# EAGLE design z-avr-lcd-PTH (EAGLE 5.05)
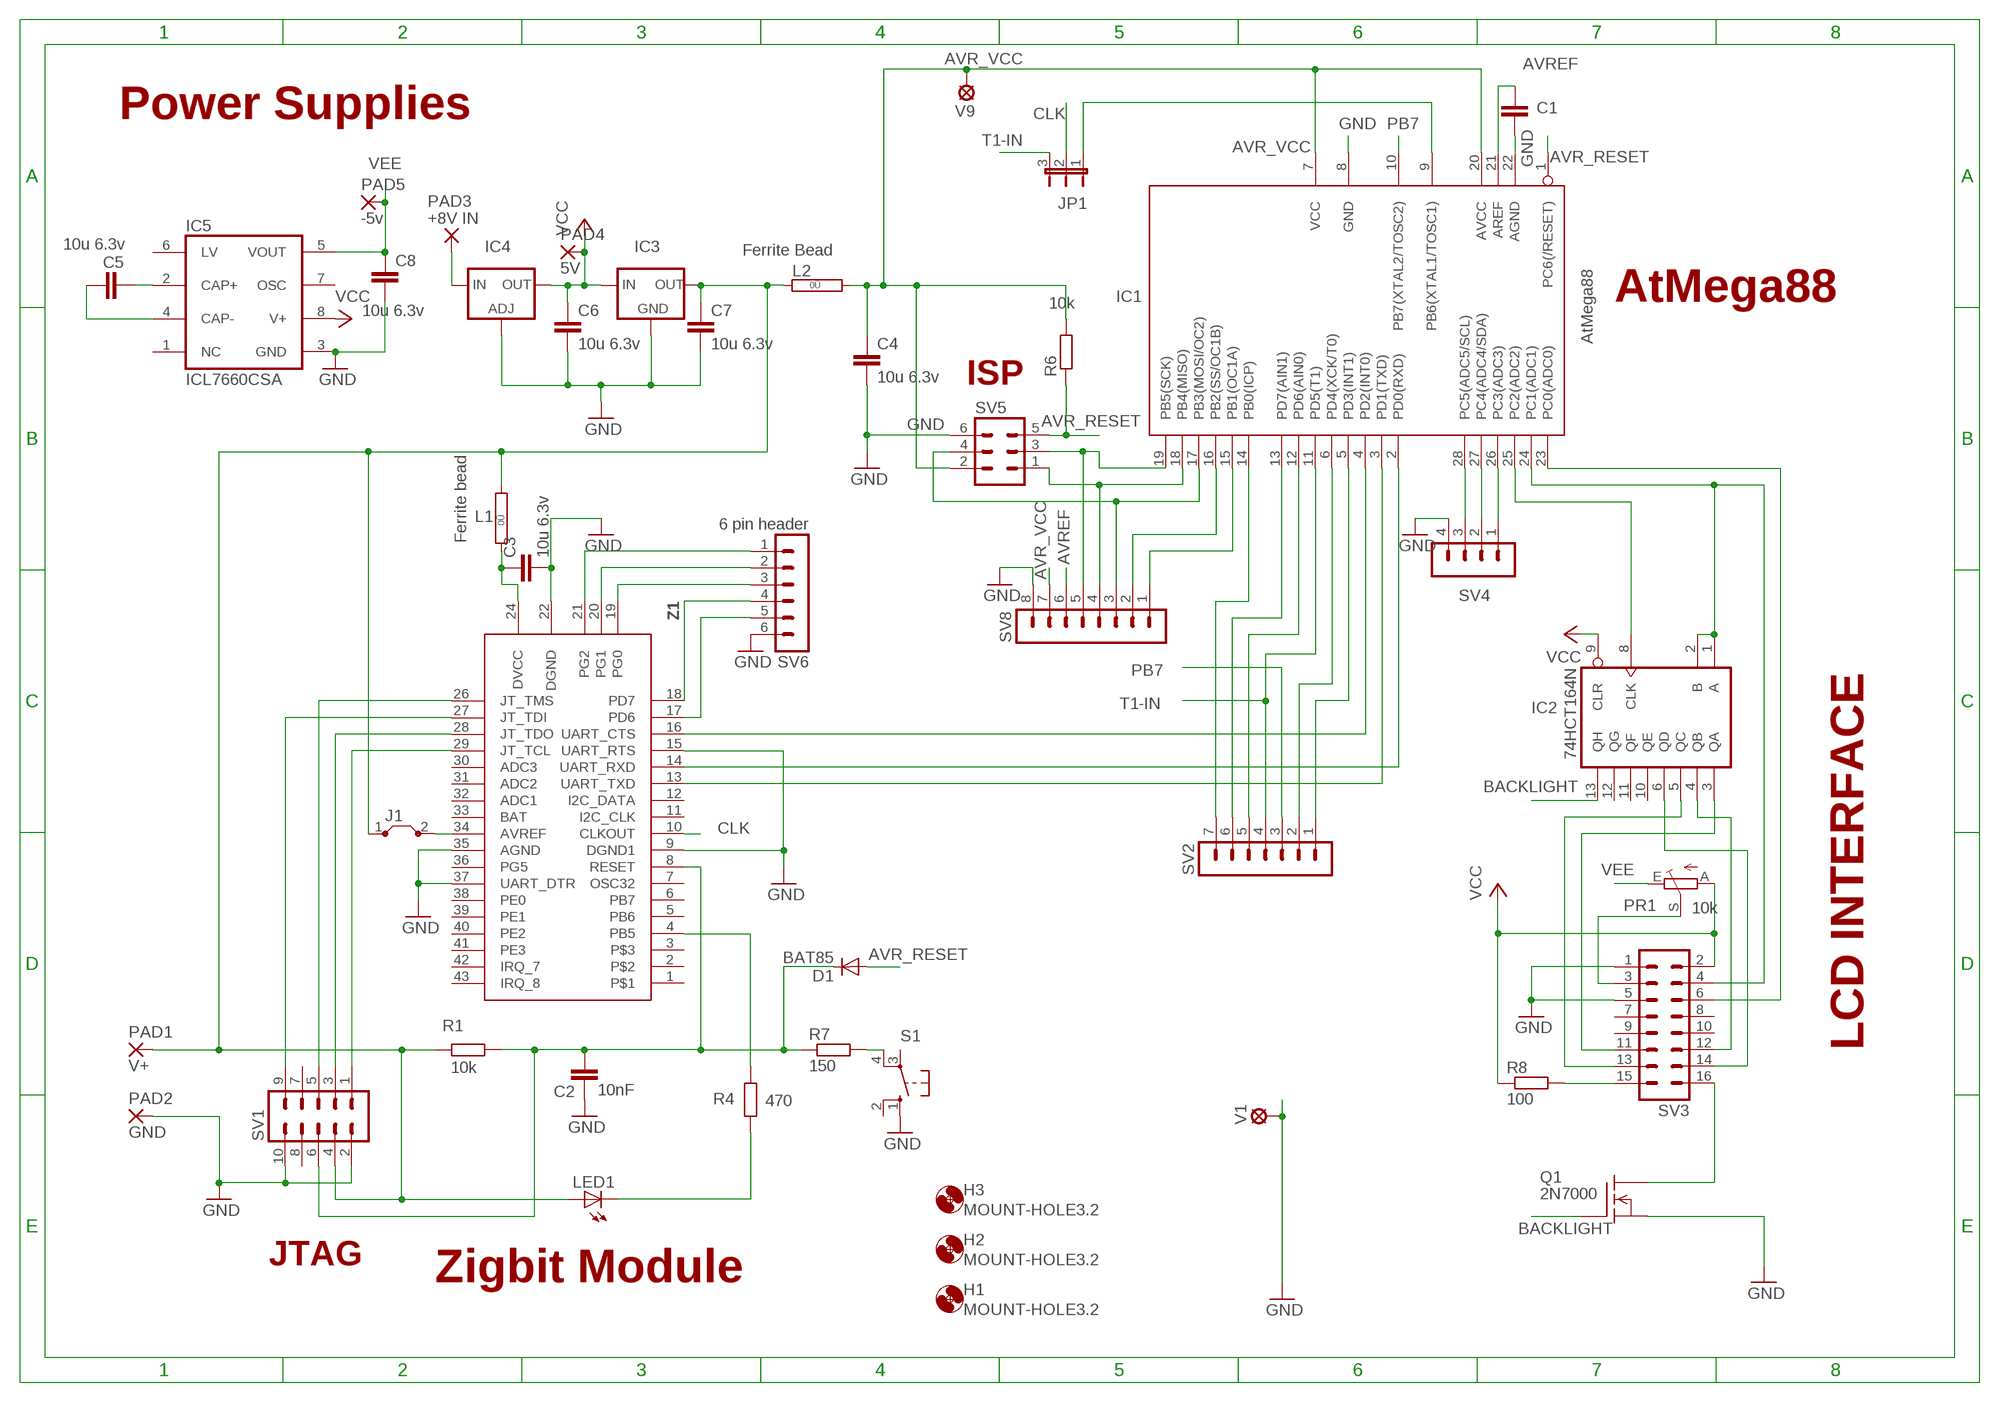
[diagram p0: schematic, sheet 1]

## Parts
C1  10y 6.3v  C-EUC1206  [C1206]
C2  10nF  C5P  [C050-030-075]
C3  10u 6.3v  C-EUC1206  [C1206]
C4  10u 6.3v  C-EUC1206  [C1206]
C5  10u 6.3v  C-EUC1206  [C1206]
C6  10u 6.3v  C-EUC1206  [C1206]
C7  10u 6.3v  C-EUC1206  [C1206]
C8  10u 6.3v  C-EUC1206  [C1206]
D1  BAT85  1N4148  [DO34-7]
H1  MOUNT-HOLE3.2  [3,2]
H2  MOUNT-HOLE3.2  [3,2]
H3  MOUNT-HOLE3.2  [3,2]
IC1  AtMega88  MEGA8-P  [DIL28-3]
IC2  74HCT164N  74ACT164N  [DIL14]
IC3  MC1702-3302E/TO 3.3V LDO VREG  XC63FPT  [TO92]
IC4  LD117ADT50TR  [DPACK]
IC5  ICL7660CSA  [SO08]
J1  J7MM  [07]
JP1  3 way Jumper  JP2E  [JP2]
L1  Ferrite bead  0R  [0R/10]
L2  Ferrite Bead  JUMPER_0R  [JUMPER_0R/10]
LED1  3MM red LED  LED-3MM3MM  [HLMP-D105]
PAD1  V+  TERMINAL-PAD  [2,54/1,1]
PAD2  GND  TERMINAL-PAD  [2,54/1,1]
PAD3  +8V IN  PAD-TERMINAL  [2,54/1,1]
PAD4  5V  TERMINAL-PAD  [2,54/1,1]
PAD5  -5v  TERMINAL-PAD  [2,54/1,1]
PR1  10k  VAR_RESISTOR_TRIMS63P  [S63P]
Q1  2N7000  [TO92]
R1  10k  R  [0207/10]
R4  470  R  [0207/10]
R6  10k  R  [0207/10]
R7  150  R  [0207/10]
R8  100  R  [0207/10]
S1  BW3-1000 PCB pushbutton  10-XX  [B3F-10XX]
SV1  10 way IDC male horiz mnt  ML10L  [ML10L]
SV2  7 way pin header  MA07-1  [MA07-1]
SV3  16 way IDC male horiz mnt  ML16L  [ML16L]
SV4  4 way pin header  MA04-1  [MA04-1]
SV5  6 way male IDC horiz mnt  ML6L  [ML6L]
SV6  6 pin header  MA06-1  [MA06-1]
SV8  8 way pin header  MA08-1  [MA08-1]
V1  HOLE-VIA"  [1,6/0,8]
V9  HOLE-VIA"  [1,6/0,8]
Z1  ZDM-A1281-A2N  [ZIGSMD]

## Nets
AVR_RESET: D1.A IC1.1(PC6(/RESET)) R6.1 SV5.5
AVR_VCC [supply]: C4.1 IC1.7(VCC) IC1.20(AVCC) L2.2 R6.2 SV5.2 SV8.7 V9.1(MP)
AVREF: C1.1 IC1.21(AREF) SV8.6
BACKLIGHT: IC2.13(QH) Q1.2(G)
CLK: JP1.2 Z1.10(CLKOUT)
GND: C1.2 C2.1 C3.2 C4.2 C6.2 C7.2 C8.2 IC1.8(GND) IC1.22(AGND) IC3.1(GND) IC4.1(ADJ) IC5.3(GND) PAD2.1(P) Q1.3(S) S1.1(S) SV1.2 SV1.10 SV3.1 SV3.5 SV4.4 SV5.6 SV6.6 SV8.8 V1.1(MP) Z1.9(DGND1) Z1.15(UART_RTS) Z1.22(DGND) Z1.35(AGND) Z1.37(UART_DTR)
N$1: IC1.18(PB4(MISO)) SV5.1 SV8.4
N$2: IC1.19(PB5(SCK)) SV5.3 SV8.5
N$3: IC1.24(PC1(ADC1)) IC2.1(A) IC2.2(B) SV3.4
N$4: IC1.25(PC2(ADC2)) IC2.8(CLK)
N$5: IC1.28(PC5(ADC5/SCL)) SV4.3
N$6: R7.2 S1.4(P1)
N$7: IC1.27(PC4(ADC4/SDA)) SV4.2
N$8: IC1.17(PB3(MOSI/OC2)) SV5.4 SV8.3
N$9: SV1.5 Z1.26(JT_TMS)
N$10: SV1.1 Z1.29(JT_TCL)
N$11: SV1.3 Z1.28(JT_TDO)
N$12: IC1.26(PC3(ADC3)) SV4.1
N$13: C2.2 D1.C R1.2 R7.1 SV1.6 Z1.8(RESET)
N$14: IC2.6(QD) SV3.14
N$15: IC1.23(PC0(ADC0)) SV3.6
N$16 [supply]: C7.1 IC3.3(OUT) J1.1 L1.2 L2.1 LED1.A PAD1.1(P) R1.1 SV1.4
N$17: C5.1 IC5.2(CAP+)
N$18: IC1.4(PD2(INT0)) Z1.16(UART_CTS)
N$19: PR1.S SV3.3
N$20: IC1.2(PD0(RXD)) Z1.14(UART_RXD)
N$21: IC1.3(PD1(TXD)) Z1.13(UART_TXD)
N$22: IC2.3(QA) SV3.11
N$23: IC2.4(QB) SV3.12
N$24: IC2.5(QC) SV3.13
N$25: C5.2 IC5.4(CAP-)
N$26: R8.2 SV3.15
N$27: Q1.1(D) SV3.16
N$28: R4.2 Z1.4(PB5)
N$29 [supply]: IC4.3(IN) PAD3.1(P)
N$30: LED1.K(C) R4.1
N$31: SV1.9 Z1.27(JT_TDI)
N$32: IC1.9(PB6(XTAL1/TOSC1)) JP1.1
N$33 [supply]: C3.1 L1.1 Z1.24(DVCC)
N$34: SV6.1 Z1.21(PG2)
N$35: SV6.2 Z1.20(PG1)
N$36: SV6.3 Z1.19(PG0)
N$37: IC1.5(PD3(INT1)) SV2.1
N$38: IC1.15(PB1(OC1A)) SV8.1
N$39: IC1.16(PB2(SS/OC1B)) SV8.2
N$40: IC1.12(PD6(AIN0)) SV2.5
N$41: IC1.13(PD7(AIN1)) SV2.6
N$42: IC1.14(PB0(ICP)) SV2.7
N$43: SV6.4 Z1.18(PD7)
N$44: IC1.6(PD4(XCK/T0)) SV2.2
N$45: SV6.5 Z1.17(PD6)
N$46: J1.2 Z1.34(AVREF)
PB7: IC1.10(PB7(XTAL2/TOSC2)) SV2.3
T1-IN: IC1.11(PD5(T1)) JP1.3 SV2.4
VCC [supply]: C6.1 IC2.9(CLR) IC3.2(IN) IC4.4(OUT) IC5.8(V+) PAD4.1(P) PR1.A R8.1 SV3.2
VEE: C8.1 IC5.5(VOUT) PAD5.1(P) PR1.E
Unconnected: IC2.10(QE) IC2.11(QF) IC2.12(QG) IC5.1(NC) IC5.6(LV) IC5.7(OSC) S1.2(S1) S1.3(P) SV1.7 SV1.8 SV3.7 SV3.8 SV3.9 SV3.10 Z1.1 Z1.2 Z1.3 Z1.5(PB6) Z1.6(PB7) Z1.7(OSC32) Z1.11(I2C_CLK) Z1.12(I2C_DATA) Z1.30(ADC3) Z1.31(ADC2) Z1.32(ADC1) Z1.33(BAT) Z1.36(PG5) Z1.38(PE0) Z1.39(PE1) Z1.40(PE2) Z1.41(PE3) Z1.42(IRQ_7) Z1.43(IRQ_8)

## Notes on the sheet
- Power Supplies
- AtMega88
- ISP
- LCD INTERFACE
- JTAG
- Zigbit Module

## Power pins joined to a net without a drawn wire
GND: IC2.7(GND)
VCC: IC2.14(VCC)

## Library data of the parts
C1 C3-C8 = rcl:C-EU: CAPACITOR, European symbol
C2 = ee2parts:C: Capacitor
D1 = ee2parts:1N4148: DIODE
H1-H3 = holes:MOUNT-HOLE: MOUNTING HOLE with drill center marker
IC1 = atmel:MEGA8-P: MICROCONTROLLER 8 Kbytes FLASH, 1 kbytes SRAM, 512 bytes EEPROM, USART, 4-channel 10 bit ADC, 2-channel 8 bit ADC Pin compatible with Atmega48, ATMega88, ATMega168 Source: avr.lbr
IC2 = 74xx-eu:74*164: 8-bit parallel out SHIFT REGISTER
IC3 = v-reg:XC63FP: Positiv Voltage Regulators www.torex.co.jp/english/product/pro02/pdf/0201_xc62fp.pdf
IC4 = v-reg:LD117A?*: Low drop fixed and adjustable positive voltage regulators 1 A Source: http://www.st.com/stonline/products/literature/ds/7194/ld1117axx.pdf
IC5 = maxim:ICL7660CSA: VOLTAGE CONVERTER
J1 = jumper:J: Bridge
JP1 = jumper:JP2E: JUMPER
L1 = jumper:0R: Bridge 0R 10mm
L2 = z-avr-lcd-noPTH:JUMPER_0R: Bridge 0R 10mm
LED1 = ee2parts:LED-3MM: LED
PAD1 PAD2 PAD4 PAD5 = ee2parts:TERMINAL-PAD: LARGE THROUGH-HOLE PAD
PAD3 = ee2parts:PAD-TERMINAL: LARGE THROUGH-HOLE PAD
PR1 = ee2parts:VAR_RESISTOR_TRIM: Variable resistor / potentiometer Trimmer potentiometer - Note that slider to end makes variable resistance
Q1 = z-avr-lcd-noPTH:2N7000: N-Channel Enhancement MOSFET 200V; 0,16A; 11Ohm
R1 R4 R6-R8 = ee2parts:R: Resistor
S1 = switch-omron:10-XX: OMRON SWITCH
SV1 = con-ml:ML10L: HARTING
SV2 = con-lstb:MA07-1: PIN HEADER
SV3 = con-ml:ML16L: HARTING
SV4 = con-lstb:MA04-1: PIN HEADER
SV5 = con-ml:ML6L: HARTING
SV6 = con-lstb:MA06-1: PIN HEADER
SV8 = con-lstb:MA08-1: PIN HEADER
V1 V9 = ee2parts:HOLE-VIA: FIXED VIA
Z1 = ee2parts:ZDM-A1281-A2

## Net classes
1 supply: width 0.889 mm

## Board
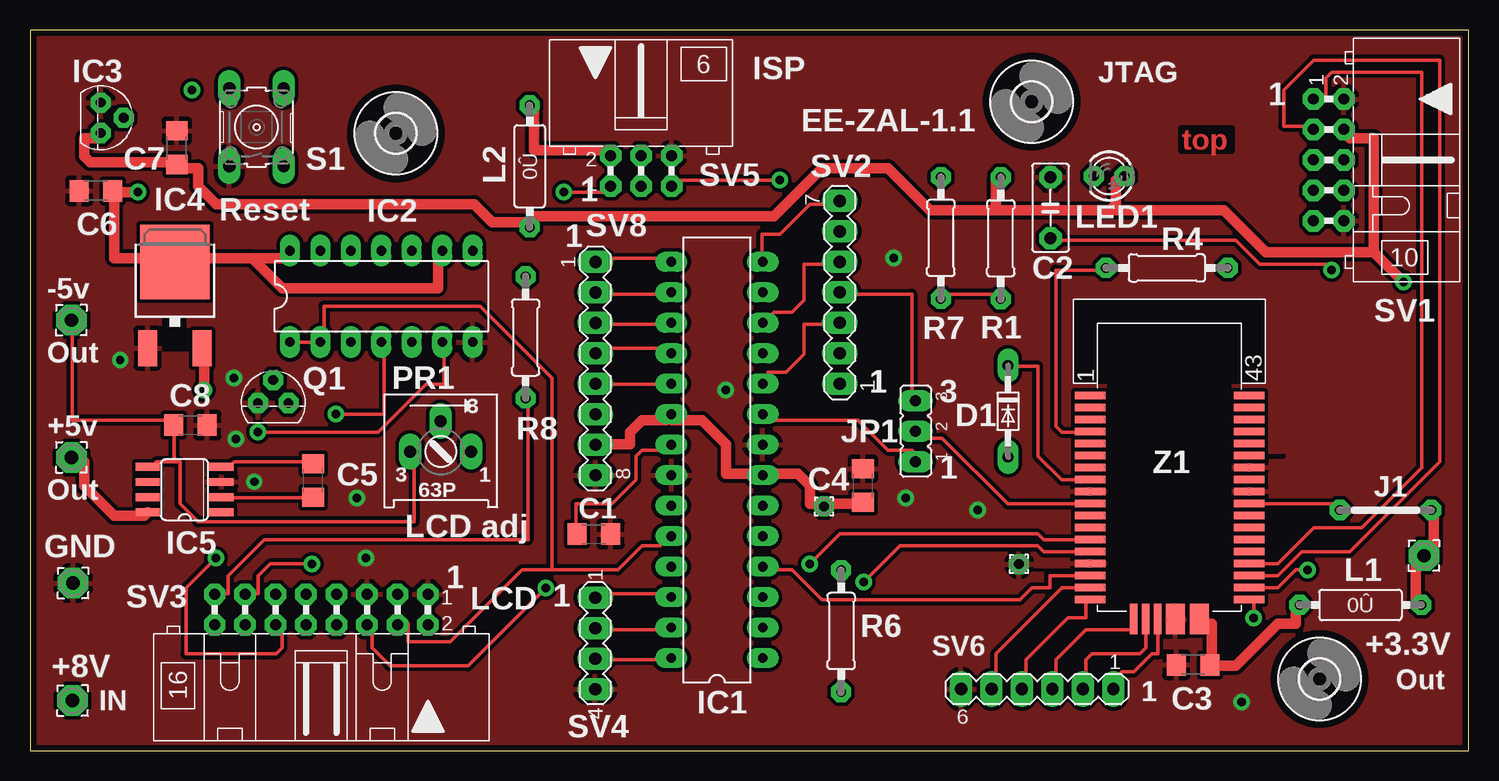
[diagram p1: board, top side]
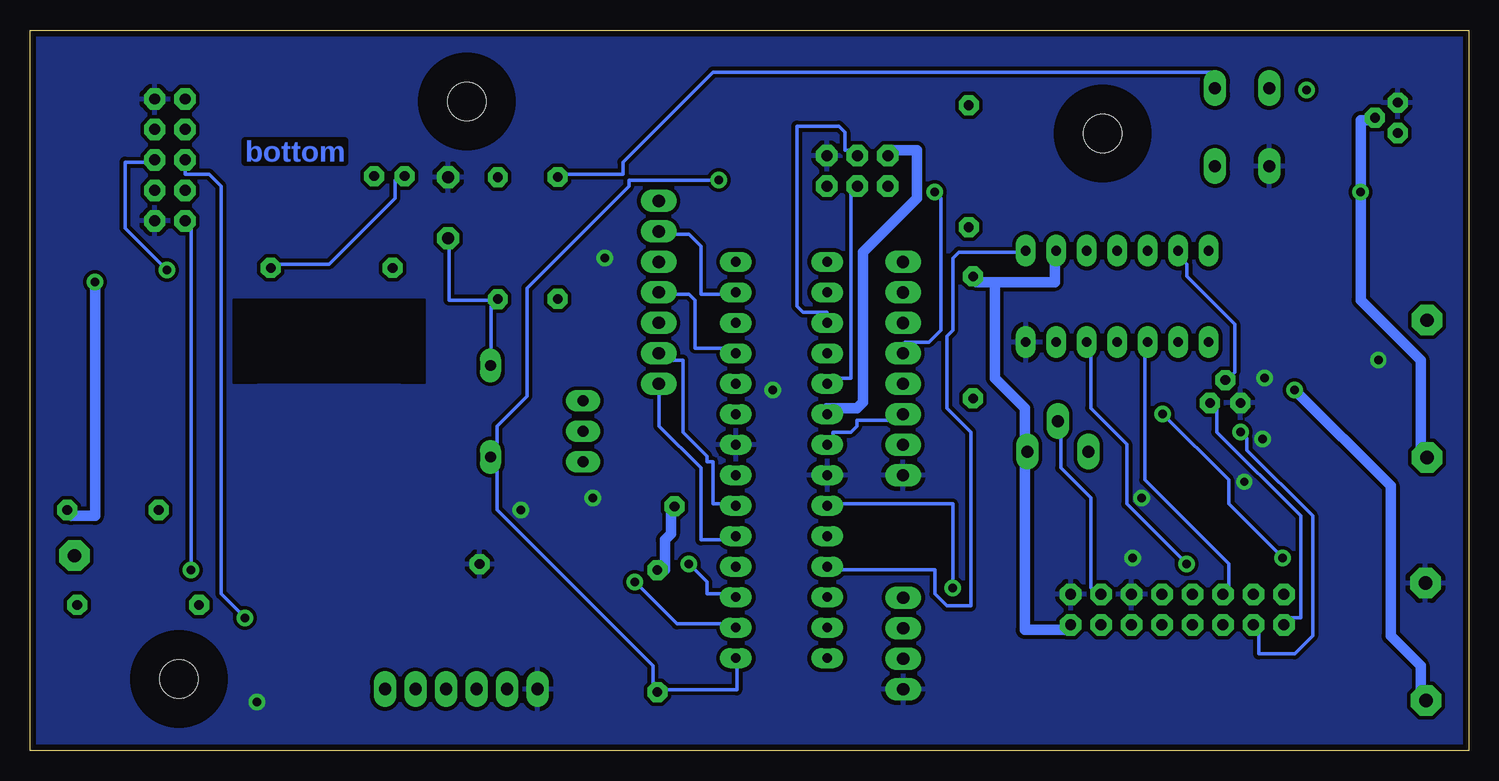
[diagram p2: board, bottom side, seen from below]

Size 119.92 x 60.07 mm. Coordinates in mm from the lower left corner, seen from the top.
Outline: 0,0 119.92,0 119.92,60.07 0,60.07 0,0
Copper layers (1*16): Top 0.035mm / dielectric 1.5mm / Bottom 0.035mm
Design rules "zigbit_rules *": minimum track width 12mil, minimum drill 0.7mm, track to track 12mil, track to pad 12mil, pad to pad 12mil, via to via 12mil, smd to smd 0mil, copper to edge 20mil, drill to drill 10mil, minimum pad ring 17mil, minimum via ring 13mil, stop-mask expansion 0mil, vias tented up to drill 0mil, thermal gap 15mil
tRestrict: area 11,33.3 to 13,36.1; 2 lines

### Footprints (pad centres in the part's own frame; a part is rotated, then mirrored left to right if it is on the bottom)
C1206 = smd 1.6 x 1.8: 1 -1.4,0; 2 1.4,0
C050-030-075 = drill 1 octagon: 1 -2.54,0; 2 2.54,0
DO34-7 = drill 0.9 long: A 3.81,0; C -3.81,0
3,2 = hole 3.2: 0,0
DIL28-3 = drill 0.813 long: 1 -16.51,-3.81; 2 -13.97,-3.81; 3 -11.43,-3.81; 4 -8.89,-3.81; 5 -6.35,-3.81; 6 -3.81,-3.81; 7 -1.27,-3.81; 8 1.27,-3.81; 9 3.81,-3.81; 10 6.35,-3.81; 11 8.89,-3.81; 12 11.43,-3.81; 13 13.97,-3.81; 14 16.51,-3.81; 15 16.51,3.81; 16 13.97,3.81; 17 11.43,3.81; 18 8.89,3.81; 19 6.35,3.81; 20 3.81,3.81; 21 1.27,3.81; 22 -1.27,3.81; 23 -3.81,3.81; 24 -6.35,3.81; 25 -8.89,3.81; 26 -11.43,3.81; 27 -13.97,3.81; 28 -16.51,3.81
DIL14 = drill 0.813 long: 1 -7.62,-3.81; 2 -5.08,-3.81; 3 -2.54,-3.81; 4 0,-3.81; 5 2.54,-3.81; 6 5.08,-3.81; 7 7.62,-3.81; 8 7.62,3.81; 9 5.08,3.81; 10 2.54,3.81; 11 0,3.81; 12 -2.54,3.81; 13 -5.08,3.81; 14 -7.62,3.81
TO92 = drill 0.813 octagon: 1 -1.27,0; 2 0,1.905; 3 1.27,0
DPACK = smd 1.6 x 3: 1 -2.28,-4.8; 3 2.28,-4.8 | smd 5.8 x 6.2: 4 0,2.38
SO08 = smd 0.66 x 2.032: 1 -1.905,-3.073; 2 -0.635,-3.073; 3 0.635,-3.073; 4 1.905,-3.073; 5 1.905,3.073; 6 0.635,3.073; 7 -0.635,3.073; 8 -1.905,3.073
07 = drill 0.813 pad 1.6 octagon: 1 -3.81,0; 2 3.81,0
JP2 = drill 0.914 long: 1 -2.54,0; 2 0,0; 3 2.54,0
0R/10 = drill 0.813 pad 1.6 octagon: 1 -5.08,0; 2 5.08,0
JUMPER_0R/10 = drill 0.813 pad 1.6 octagon: 1 -5.08,0; 2 5.08,0
HLMP-D105 = drill 0.8 octagon: A -1.27,0; K 1.27,0
2,54/1,1 = drill 1.118 pad 2.54 octagon: 1 0,0
S63P = drill 1 long: A 2.54,0; E -2.54,0; S 0,2.54
TO92' = drill 0.813 octagon: 1 1.27,0; 2 0,1.905; 3 -1.27,0
0207/10 = drill 0.8 octagon: 1 -5.08,0; 2 5.08,0
B3F-10XX = drill 1.016 long: 1 -3.251,2.261; 2 3.251,2.261; 3 -3.251,-2.261; 4 3.251,-2.261
ML10L = drill 0.914 octagon: 1 -5.08,-1.27; 2 -5.08,1.27; 3 -2.54,-1.27; 4 -2.54,1.27; 5 0,-1.27; 6 0,1.27; 7 2.54,-1.27; 8 2.54,1.27; 9 5.08,-1.27; 10 5.08,1.27
MA07-1 = drill 1.016 long: 1 -7.62,0; 2 -5.08,0; 3 -2.54,0; 4 0,0; 5 2.54,0; 6 5.08,0; 7 7.62,0
ML16L = drill 0.914 octagon: 1 -8.89,-1.27; 2 -8.89,1.27; 3 -6.35,-1.27; 4 -6.35,1.27; 5 -3.81,-1.27; 6 -3.81,1.27; 7 -1.27,-1.27; 8 -1.27,1.27; 9 1.27,-1.27; 10 1.27,1.27; 11 3.81,-1.27; 12 3.81,1.27; 13 6.35,-1.27; 14 6.35,1.27; 15 8.89,-1.27; 16 8.89,1.27
MA04-1 = drill 1.016 long: 1 -3.81,0; 2 -1.27,0; 3 1.27,0; 4 3.81,0
ML6L = drill 0.914 octagon: 1 -2.54,-1.27; 2 -2.54,1.27; 3 0,-1.27; 4 0,1.27; 5 2.54,-1.27; 6 2.54,1.27
MA06-1 = drill 1.016 long: 1 -6.35,0; 2 -3.81,0; 3 -1.27,0; 4 1.27,0; 5 3.81,0; 6 6.35,0
MA08-1 = drill 1.016 long: 1 -8.89,0; 2 -6.35,0; 3 -3.81,0; 4 -1.27,0; 5 1.27,0; 6 3.81,0; 7 6.35,0; 8 8.89,0
1,6/0,8 = drill 0.813 pad 1.6 octagon: 1 0,0
ZIGSMD = smd 0.635 x 2.54: 1 7,6.635; 2 6,6.635; 3 5,6.635; 4 4,6.635; 5 3,6.635; 6 2,6.635; 7 1,6.635; 8 0,6.635; 9 -1,6.635; 10 -2,6.635; 11 -3,6.635; 12 -4,6.635; 13 -5,6.635; 14 -6,6.635; 15 -7,6.635; 16 -8,6.635; 17 -9,6.635; 18 -10,6.635; 26 -10,-6.635; 27 -9,-6.635; 28 -8,-6.635; 29 -7,-6.635; 30 -6,-6.635; 31 -5,-6.635; 32 -4,-6.635; 33 -3,-6.635; 34 -2,-6.635; 35 -1,-6.635; 36 0,-6.635; 37 1,-6.635; 38 2,-6.635; 39 3,-6.635; 40 4,-6.635; 41 5,-6.635; 42 6,-6.635; 43 7,-6.635 | smd 2.54 x 0.635: 19 -11.635,3; 20 -11.635,2; 21 -11.635,1 | smd 2.54 x 1.6: 22 -11.635,-0.5; 24 -11.635,-2.5

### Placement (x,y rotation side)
C1  47,18.07 0 top
C2  85.07,45.26 270 top
C3  96.96,7.16 180 top
C4  69.44,22.11 90 top
C5  23.61,22.52 90 top
C6  5.5,46.66 180 top
C7  12.24,50.27 90 top
C8  13.38,27.15 0 top
D1  81.53,28.3 270 top
H1  107.5,5.99 0 top
H2  83.5,54.1 0 top
H3  30.5,51.46 0 top
IC1  57.27,24.24 90 top
IC2  29.29,37.87 0 top
IC3  5.9,52.75 270 top
IC4  12.08,38.35 0 top
IC5  12.89,21.77 90 top
J1  113,20.07 180 top
JP1  73.82,26.64 90 top
L1  110.91,12.16 0 top
L2  41.66,48.72 90 top
LED1  89.96,47.89 180 top
PAD1  116.2,16.26 0 top
PAD2  3.59,13.98 90 top
PAD3  3.55,4.18 0 top
PAD4  3.45,24.45 0 top
PAD5  3.45,35.88 0 top
PR1  34.24,24.94 0 top
Q1  2N7000  [TO92']  20.28,28.99 0 top
R1  80.92,42.72 270 top
R4  94.77,40.24 180 top
R6  67.62,9.98 90 top
R7  75.93,42.74 90 top
R8  41.31,34.45 270 top
S1  18.88,51.97 90 top
SV1  108.26,49.24 270 top
SV2  67.51,38.2 90 top
SV3  24.28,11.77 180 top
SV4  47.12,8.95 270 top
SV5  50.95,48.33 0 top
SV6  83.97,5.15 180 top
SV8  47.14,31.85 270 top
V1  82.45,15.56 0 top
V9  66.19,20.37 0 top
Z1  94.99,22.61 90 top

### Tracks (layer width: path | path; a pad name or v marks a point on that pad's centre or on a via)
AVR_RESET  (via drill 0.7)
  Top 0.305: v62.5,47.57 54,47.57 SV5.5
  Bottom 0.305: IC1.1 61,7.57 61,5.07 67.5,5.07 R6.1 68,5.07 68,7.07 81,20.07 81,23.57 | 81,23.57 81.5,24.07 D1.A 81,23.57 | v62.5,47.57 70,47.57 70,47.07 78.5,38.57 78.5,29.57 81,27.07 81,23.57
AVR_VCC
  Top 0.889: L2.2 42,53.57 42,50.07 48,50.07 SV5.2 | SV8.7 47.5,25.57 50,25.57 50,26.57 51,27.57 53,27.57 IC1.20 53.5,27.57 56,27.57 58,25.57 58,23.07 61,23.07 IC1.7 61.5,23.07 64,23.07 65,22.07 65,20.57 66,20.57 V9.1 66.5,20.57 69,20.57 C4.1
  Bottom 0.889: R6.2 67.5,15.07 67,15.07 67,17.57 66.5,18.07 66.5,20.07 V9.1 | SV5.2 48,50.07 46,50.07 46,46.07 50.5,41.57 50.5,29.07 51,28.57 53.5,28.57 53.5,28.07 IC1.20
AVREF
  Top 0.305: C1.1 45.5,18.07 45.5,20.57 48.5,20.57 50.5,22.57 50.5,24.57 51,25.07 53,25.07 IC1.21
  Bottom 0.305: SV8.6 47.5,27.57 51,27.57 51,27.07 51.5,26.57 53,26.57 53,25.57 IC1.21
BACKLIGHT
  Bottom 0.305: Q1.2 20,31.07 19.5,31.57 19.5,35.57 23.5,39.57 23.5,40.57 24,41.07 24,41.57 IC2.13
CLK
  Top 0.305: Z1.10 88,20.57 81.5,20.57 76,26.07 74.5,26.07 74,26.57 JP1.2
GND  (via drill 0.7)
  other vias: 17.17,25.98 18.69,22.42 7.52,32.58 17,31.07 28,16.07 27.25,21.07 73,21.07 72,41.07 79,20.07 101,4.07 58,30.07
  pour Bottom: 0.25,59.82 119.67,59.82 119.67,0.25 0.25,0.25
  pour Top: 0.25,59.82 119.67,59.82 119.67,0.25 0.25,0.25
N$1  (via drill 0.7)
  Top 0.305: IC1.18 53,33.57 47.5,33.57 SV8.4 | v44.5,46.57 48,46.57 SV5.1
  Bottom 0.305: v44.5,46.57 44,46.07 44,35.07 45,34.07 47,34.07 47,33.57 SV8.4
N$2
  Top 0.305: IC1.19 53,30.57 47.5,30.57 SV8.5
  Bottom 0.305: SV5.3 51,46.57 51.5,46.57 51.5,31.07 53,31.07 IC1.19
N$3
  Top 0.305: IC2.1 22,34.07 24,34.07 IC2.2 24.5,34.07 24.5,37.07 37.5,37.07 43.5,31.07 43.5,15.07 | 43.5,15.07 41,15.07 35,9.07 31.5,9.07 31.5,10.57 31,10.57 SV3.4 | 43.5,15.07 49,15.07 51,17.07 52.5,17.07 53,17.57 IC1.24
N$4
  Bottom 0.305: IC1.25 53,15.07 44.5,15.07 44.5,13.07 43.5,12.07 41.5,12.07 41.5,26.57 43.5,28.57 43.5,34.57 43,35.07 43,41.07 42.5,41.57 37,41.57 IC2.8
N$5
  Top 0.305: IC1.28 53,7.57 47.5,7.57 SV4.3
N$6
  Bottom 0.305: R7.2 75.5,48.07 70.5,48.07 70.5,49.07 63,56.57 21.5,56.57 21.5,55.57 S1.4
N$7
  Top 0.305: IC1.27 53,10.07 47.5,10.07 SV4.2
N$8
  Top 0.305: IC1.17 53,35.57 47.5,35.57 SV8.3
  Bottom 0.305: SV5.4 51,50.07 52,50.07 52,51.57 52.5,52.07 56,52.07 56,37.07 55.5,36.57 53.5,36.57 53.5,36.07 IC1.17
N$9  (via drill 0.7)
  Top 0.305: v102,11.07 102,12.57 Z1.26
  Bottom 0.305: v102,11.07 104,13.07 104,47.07 105,48.07 107,48.07 107,49.07 SV1.5
N$10
  Top 0.305: Z1.29 102,15.57 104,15.57 107,18.57 111,18.57 116,23.57 116,56.57 108.5,56.57 108,56.07 108,54.57 107,54.57 SV1.1
N$11
  Top 0.305: Z1.28 102,14.57 104,14.57 106,16.57 110,16.57 117.5,24.07 117.5,57.57 107,57.57 104.5,55.07 104.5,52.07 106.5,52.07 SV1.3
N$12
  Top 0.305: IC1.26 53,13.07 47.5,13.07 SV4.1
N$13  (via drill 0.7)
  Top 0.305: R1.2 80.5,38.07 76,38.07 R7.1 | Z1.8 88,22.57 86,22.57 84,24.57 84,32.07 82,32.07 D1.C | v108.5,40.07 108,40.57 102.5,40.57 100.5,42.57 85.5,42.57 C2.2
  Bottom 0.305: 81,37.57 81.5,37.07 81.5,32.57 D1.C | v108.5,40.07 112,43.57 112,49.07 110,49.07 SV1.6 | 81,37.57 85,37.57 85,42.57 C2.2 | 81,37.57 R1.2
N$14  (via drill 0.7)
  Top 0.305: v19,26.57 29,26.57 33,30.57 34.5,30.57 34.5,33.57 IC2.6
  Bottom 0.305: v19,26.57 18.5,26.07 18.5,25.07 13,19.57 13,9.57 14.5,8.07 17.5,8.07 17.5,10.07 SV3.14
N$15  (via drill 0.7)
  Top 0.305: v43,13.57 36.5,7.07 30,7.07 28.5,8.57 28.5,10.07 SV3.6
  Bottom 0.305: v43,13.57 43,20.57 53,20.57 IC1.23
N$16  (via drill 0.7)
  Top 0.889: IC3.3 5.5,51.07 4.5,51.07 4.5,49.57 5,49.07 12,49.07 C7.1 12.5,48.57 14,48.57 14,47.07 15.5,45.57 37,45.57 38.5,44.07 41.5,44.07 L2.1 42,44.07 42,44.57 62,44.57 66,48.57 71.5,48.57 75,45.07 80.5,45.07 | L1.2 115.5,12.57 115.5,16.07 116,16.07 PAD1.1 116.5,16.57 117,16.57 117,19.57 J1.1 | 80.5,45.07 80.5,47.57 R1.1 | 80.5,45.07 90,45.07 90.25,45.32 | 90.25,45.32 90.5,45.57 90.5,47.57 91,47.57 LED1.A | 112,41.57 112,51.07 110,51.07 110,51.57 SV1.4 | 112,41.57 103,41.57 99.5,45.07 90.5,45.07 90.25,45.32 | 112,41.57 v114.5,39.07
  Bottom 0.889: v114.5,39.07 114.5,19.57 116.5,19.57 J1.1
N$17
  Top 0.305: C5.1 23.5,21.07 16,21.07 IC5.2
N$18
  Top 0.305: Z1.16 88,14.57 85,14.57 85,13.57 83.5,13.57 82.5,12.57 66,12.57 63.5,15.07 61.5,15.07 IC1.4
N$19
  Bottom 0.305: SV3.3 31,13.07 31.5,13.57 31.5,21.07 34,23.57 34,27.07 PR1.S
N$20  (via drill 0.7)
  Top 0.305: v69.5,14.07 72.5,17.07 84,17.07 84.5,16.57 88,16.57 Z1.14
  Bottom 0.305: v69.5,14.07 66,10.57 61.5,10.57 IC1.2
N$21  (via drill 0.7)
  Top 0.305: v65,15.57 67.5,18.07 84,18.07 84.5,17.57 88,17.57 Z1.13
  Bottom 0.305: v65,15.57 63.5,14.07 63.5,13.07 61.5,13.07 IC1.3
N$22
  Bottom 0.305: IC2.3 27,33.57 27,22.57 20,15.57 20,13.07 SV3.11
N$23  (via drill 0.7)
  Top 0.305: v25.5,28.07 29.5,28.07 29.5,33.57 IC2.4 | v15.5,16.07 13,13.57 13,8.07 20.5,8.07 21,8.57 21,10.07 20.5,10.07 SV3.12
  Bottom 0.305: v25.5,28.07 20,22.57 20,20.57 v15.5,16.07
N$24  (via drill 0.7)
  Top 0.305: v23.5,15.57 20,15.57 19,14.57 19,13.07 18,13.07 SV3.13
  Bottom 0.305: v23.5,15.57 28.5,20.57 28.5,25.57 31.5,28.57 31.5,33.57 IC2.5
N$25
  Top 0.305: C5.2 23.5,24.07 17,24.07 16.5,23.57 16,23.57 IC5.4
N$26
  Top 0.305: R8.2 41.5,29.07 41.5,17.57 19.5,17.57 16.5,14.57 16.5,13.07 15.5,13.07 SV3.15
N$27
  Bottom 0.305: Q1.1 21.5,28.57 21,28.57 21,26.57 14,19.57 14,11.07 15,11.07 15,10.57 SV3.16
N$28
  Top 0.305: Z1.4 88,26.57 86,26.57 85.5,27.07 85.5,40.07 89.5,40.07 R4.2
N$29  (via drill 0.7)
  Top 0.889: v14.5,30.07 14.5,33.07 IC4.3
  Bottom 0.889: v14.5,30.07 6.5,22.07 6.5,9.57 4,7.07 4,4.57 PAD3.1
N$30
  Bottom 0.305: LED1.K 89,47.57 89.5,47.57 89.5,46.07 95,40.57 99.5,40.57 R4.1
N$31  (via drill 0.7)
  Top 0.305: v106.5,15.07 105.5,15.07 104,13.57 102,13.57 Z1.27
  Bottom 0.305: v106.5,15.07 106.5,44.07 SV1.9
N$32
  Top 0.305: IC1.9 61.5,27.57 69,27.57 71.5,25.07 73.5,25.07 74,24.57 JP1.1
N$33
  Top 0.889: Z1.24 97.5,10.57 98.5,10.57 98.5,7.57 C3.1 98.5,7.07 100.5,7.07 104,10.57 105.5,10.57 105.5,12.07 L1.1
N$34
  Top 0.305: Z1.21 94,10.57 94,8.07 93.5,8.07 92,6.57 91,6.57 90,5.57 SV6.1
N$35
  Top 0.305: Z1.20 93,10.57 93,8.57 92.5,8.07 88.5,8.07 88,7.57 88,5.57 SV6.2
N$36
  Top 0.305: Z1.19 92,10.57 92,10.07 88,10.07 85.5,7.57 85.5,5.57 SV6.3
N$37
  Bottom 0.305: IC1.5 61.5,17.57 64,17.57 64,23.57 67.5,27.07 SV2.1
N$38
  Top 0.305: IC1.15 53,41.07 47.5,41.07 SV8.1
N$39
  Top 0.305: IC1.16 53,38.07 47.5,38.07 SV8.2
N$40
  Top 0.305: IC1.12 61.5,36.07 62,36.57 63.5,36.57 64.5,37.57 64.5,40.57 67.5,40.57 SV2.5
N$41
  Bottom 0.305: IC1.13 61.5,38.07 64,38.07 64,42.07 65,43.07 67.5,43.07 SV2.6
N$42
  Top 0.305: IC1.14 61,41.07 61,43.07 62.5,43.07 65,45.57 67.5,45.57 SV2.7
N$43
  Top 0.305: Z1.18 88,12.57 88,11.07 86.5,11.07 83,7.57 83,5.57 SV6.4
N$44
  Bottom 0.305: IC1.6 61.5,20.57 63,20.57 63,24.07 63.5,24.07 63.5,24.57 65.5,26.57 65.5,32.57 67.5,32.57 67.5,33.07 SV2.2
N$45
  Top 0.305: Z1.17 88,13.57 86,13.57 80.5,8.07 80.5,5.57 SV6.5
N$46
  Top 0.305: Z1.34 102,20.57 109,20.57 109.5,20.07 J1.2
PB7
  Top 0.305: IC1.10 61.5,31.07 61.5,31.57 63,31.57 64.5,33.07 64.5,35.57 67.5,35.57 SV2.3
T1-IN
  Top 0.305: JP1.3 73.5,29.57 73.5,38.07 68,38.07 SV2.4
  Bottom 0.305: IC1.11 61.5,33.57 64.5,33.57 64.5,37.57 65,38.07 67.5,38.07 SV2.4
VCC  (via drill 0.7)
  Top 0.889: IC5.8 9.5,19.57 7,19.57 4.5,22.07 4.5,24.07 3.5,24.07 PAD4.1 | 7,46.57 7,41.07 12,41.07 IC4.4 12.5,41.07 18.5,41.07 | 18.5,41.07 21.5,41.07 21.5,41.57 IC2.14 | 7,46.57 v9,46.57 | 7,46.57 C6.1 | 18.5,41.07 21,38.57 34,38.57 34,41.57 IC2.9
  Bottom 0.889: 39.5,39.07 34.5,39.07 34.5,41.57 IC2.9 | 39.5,39.07 41,39.07 R8.1 | SV3.2 33.5,10.07 37,10.07 37,24.57 PR1.A 37,25.07 37,28.57 39.5,31.07 39.5,39.07 | IC3.2 8,52.57 9,52.57 v9,46.57 9,37.57 4,32.57 4,25.07 3.5,24.57 PAD4.1
VEE
  Top 0.305: 12,24.07 12,27.07 C8.1 11.5,27.57 3.5,27.57 3.5,35.57 PAD5.1 | 12,24.07 10.5,24.07 10,23.57 IC5.5 | 12,24.07 12.5,24.07 12.5,20.57 14,19.07 32,19.07 32,24.57 PR1.E
XX  (via drill 0.7)
  other vias: 13.5,55.07

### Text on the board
Top: top
Bottom: bottom
tNames: IC3 | ISP | JTAG | 1 | EE-ZAL-1.1 | S1 | 1 | Reset | 1 | -5v | Out | 1 | 3 | +5v | 1 | Out | LCD adj | 1 | LCD | 1 | +8V | +3.3V | Out | 1 | IN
